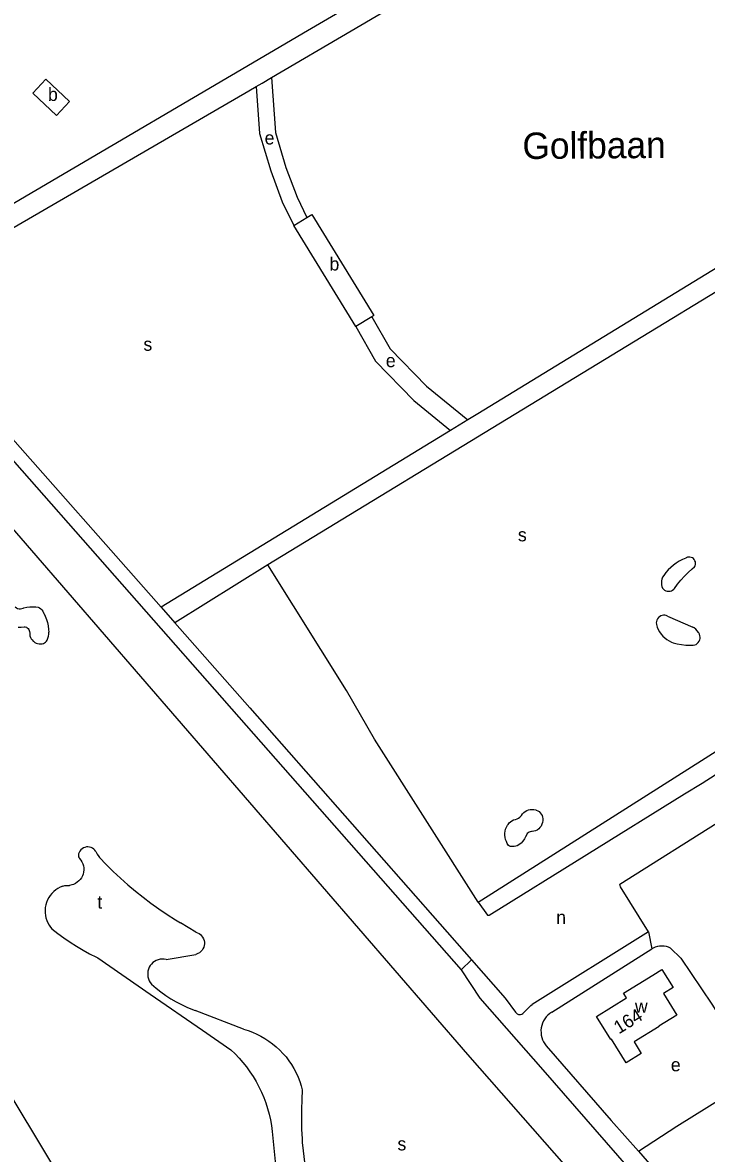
# Model space of a CAD drawing. Extents: x 156066 to 157805, y 383432 to 385631.
# Drawn here: x 157183.1 to 157390.3, y 384159.6 to 384502.5 of the extents above; entities that cross this region are included whole.
import ezdxf

# ---------------------------------------------------------------- set-up
doc = ezdxf.new("R2010")
doc.units = 0
for name, color, linetype in [('BLT_Basislijn', 7, 'Continuous'), ('BLT_Bebouwing', 7, 'Continuous'), ('BLT_Centroide', 7, 'Continuous'), ('BLT_Huisnummer', 7, 'Continuous'), ('BLT_Terrein_beschrifting', 7, 'Continuous'), ('BLT_Vlakafsluiter', 7, 'Continuous')]:
    doc.layers.add(name, color=color, linetype=linetype)

msp = doc.modelspace()

# ---------------------------------------------------------------- linework, layer by layer
at = {"layer": 'BLT_Basislijn'}
for p, q in [((157269.37, 384500), (157138.64, 384423.17)), ((157258.52, 384485.83), (157282.62, 384500)), ((157251.62, 384481.8), (157253.88, 384483.11)), ((157153.14, 384424.57), (157251.62, 384481.8)), ((157148.04, 384412.49), (157225.04, 384325.21)), ((157161.96, 384390.33), (157250.85, 384289.34)), ((157321.03, 384383.89), (157317.99, 384382.04)), ((157317.99, 384382.04), (157312.77, 384378.85)), ((157312.77, 384378.85), (157225.04, 384325.21)), ((157257.34, 384338.04), (157229.21, 384320.49)), ((157225.04, 384325.21), (157229.21, 384320.49)), ((157378.52, 384322.55), (157386.16, 384319.23)), ((157229.21, 384320.49), (157251.97, 384294.7)), ((157388.98, 384271.84), (157431.02, 384299.07)), ((157251.97, 384294.7), (157319.12, 384218.27)), ((157250.85, 384289.34), (157315.94, 384215.28)), ((157235.57, 384226.69), (157230.92, 384229.54)), ((157372.75, 384226.84), (157337.45, 384204.77)), ((157343.39, 384202.41), (157373.72, 384221.64)), ((157379.44, 384221.88), (157382.55, 384218.81)), ((157226.53, 384218.43), (157235.57, 384219.98)), ((157315.94, 384215.28), (157319.12, 384218.27)), ((157319.12, 384218.27), (157329.29, 384206.7)), ((157329.29, 384206.7), (157332.46, 384202.4)), ((157250.02, 384197.26), (157235.31, 384202.94)), ((157341.76, 384192.28), (157361.44, 384169.6)), ((157340.74, 384184.93), (157372.94, 384148.06)), ((157361.44, 384169.6), (157369.67, 384160.28)), ((157267.82, 384162.92), (157269.11, 384151.56)), ((157369.67, 384160.28), (157381.29, 384147.11))]:
    msp.add_line(p, q, dxfattribs=at)
for points in [[(157282.62, 384500), (157336.87, 384531.91)], [(157292.9, 384513.83), (157269.37, 384500)], [(157511.3, 384500), (157466.93, 384473.08), (157321.03, 384383.89)], [(157463.86, 384023.42), (157317.96, 384189.64), (157152.75, 384380.64), (157052.19, 384495.7)], [(157253.88, 384483.11), (157255.67, 384484.15), (157258.52, 384485.83)], [(157258.52, 384485.83), (157259.71, 384469.14), (157262.87, 384458.55), (157266.24, 384449.53), (157269.21, 384443.41)], [(157253.88, 384483.11), (157254.89, 384468.85), (157258.25, 384457.56), (157261.77, 384448.17), (157265.25, 384440.98)], [(157321.16, 384235.84), (157422.22, 384300), (157452.28, 384318.94), (157454.21, 384323.92), (157457.87, 384326.37), (157459.12, 384328.47), (157459.31, 384329.8), (157458.83, 384332.42), (157438.86, 384363.06), (157437.2, 384366.69), (157437.22, 384369.84), (157438.41, 384372.18), (157439.25, 384373.17), (157441.31, 384374.78), (157456.44, 384383.06), (157457.87, 384385.19), (157457.71, 384388.47), (157426.03, 384440.3), (157425.29, 384440.34), (157257.34, 384338.04)], [(157284.04, 384410.33), (157289.99, 384399.85), (157301.67, 384387.92), (157312.77, 384378.85)], [(157288.87, 384413.29), (157294.4, 384403.57), (157305.43, 384392.3), (157317.99, 384382.04)], [(157321.16, 384235.84), (157289.75, 384285.23), (157281.24, 384300), (157257.34, 384338.04)], [(157384, 384340.14), (157383.01, 384339.71), (157382.07, 384339.21), (157381.16, 384338.64), (157380.29, 384338), (157379.48, 384337.3), (157378.72, 384336.55), (157378.02, 384335.73), (157377.38, 384334.87), (157377.01, 384334.3)], [(157386.67, 384337.47), (157386.85, 384337.82), (157386.96, 384338.2), (157386.99, 384338.59), (157386.94, 384338.98), (157386.81, 384339.35), (157386.61, 384339.68), (157386.35, 384339.97), (157386.03, 384340.2), (157385.67, 384340.36), (157385.29, 384340.45), (157384.9, 384340.46), (157384.52, 384340.39), (157384.15, 384340.24), (157384, 384340.14)], [(157380.61, 384330.91), (157381.56, 384332.21), (157382.57, 384333.46), (157383.64, 384334.65), (157384.77, 384335.79), (157385.96, 384336.88), (157386.67, 384337.47)], [(157377.01, 384334.3), (157376.8, 384333.77), (157376.67, 384333.21), (157376.62, 384332.63), (157376.65, 384332.06), (157376.76, 384331.5), (157376.94, 384330.99)], [(157376.94, 384330.99), (157377.23, 384330.67), (157377.58, 384330.41), (157377.97, 384330.22), (157378.39, 384330.1), (157378.82, 384330.07), (157379.25, 384330.11), (157379.67, 384330.23), (157380.05, 384330.43), (157380.4, 384330.69), (157380.61, 384330.91)], [(157180.82, 384325.32), (157181.17, 384325.07), (157181.56, 384324.89), (157181.98, 384324.79), (157182.41, 384324.77), (157182.84, 384324.82), (157183.25, 384324.96), (157183.42, 384325.04)], [(157183.42, 384325.04), (157184.31, 384325.23), (157185.21, 384325.34), (157186.12, 384325.37), (157187.03, 384325.33), (157187.74, 384325.23)], [(157187.74, 384325.23), (157188.18, 384325.02), (157188.58, 384324.74), (157188.93, 384324.4), (157189.22, 384324.01), (157189.44, 384323.57), (157189.48, 384323.47)], [(157189.48, 384323.47), (157189.92, 384322.53), (157190.29, 384321.56), (157190.58, 384320.57), (157190.8, 384319.55), (157190.93, 384318.52), (157190.99, 384317.69)], [(157378.52, 384322.55), (157378.12, 384322.71), (157377.69, 384322.8), (157377.26, 384322.8), (157376.83, 384322.73), (157376.42, 384322.58), (157376.05, 384322.36), (157375.73, 384322.07), (157375.46, 384321.73), (157375.26, 384321.35), (157375.13, 384320.93), (157375.08, 384320.5), (157375.11, 384320.07), (157375.13, 384319.95)], [(157181.74, 384319.22), (157182.62, 384319.19), (157183.55, 384319.25)], [(157183.55, 384319.25), (157183.88, 384319.25), (157184.2, 384319.17), (157184.49, 384319.01), (157184.73, 384318.79), (157184.95, 384318.44)], [(157184.95, 384318.44), (157185.12, 384317.91), (157185.21, 384317.36), (157185.23, 384317.02)], [(157190.48, 384315.25), (157190.73, 384315.83), (157190.89, 384316.42), (157190.98, 384317.04), (157190.99, 384317.69)], [(157375.13, 384319.95), (157375.38, 384319.19), (157375.7, 384318.46), (157376.09, 384317.76), (157376.55, 384317.1), (157377.07, 384316.49), (157377.65, 384315.94), (157378.29, 384315.45), (157378.96, 384315.03), (157379.68, 384314.67), (157380.18, 384314.47)], [(157387.89, 384317.57), (157387.52, 384318.09), (157387.08, 384318.55), (157386.59, 384318.95), (157386.16, 384319.23)], [(157386.3, 384313.68), (157386.73, 384313.79), (157387.14, 384313.97), (157387.5, 384314.22), (157387.81, 384314.54), (157388.06, 384314.9), (157388.25, 384315.3), (157388.35, 384315.73), (157388.38, 384316.18), (157388.33, 384316.61), (157388.2, 384317.04), (157387.99, 384317.43), (157387.89, 384317.57)], [(157185.23, 384317.02), (157185.29, 384316.55), (157185.43, 384316.1), (157185.65, 384315.68), (157185.93, 384315.3), (157186.27, 384314.98), (157186.43, 384314.86)], [(157186.43, 384314.86), (157186.78, 384314.58), (157187.17, 384314.36), (157187.6, 384314.21), (157188.04, 384314.14), (157188.58, 384314.16)], [(157188.58, 384314.16), (157188.98, 384314.18), (157189.36, 384314.27), (157189.72, 384314.43), (157190.04, 384314.67), (157190.3, 384314.96), (157190.48, 384315.25)], [(157380.18, 384314.47), (157381.44, 384314.16), (157382.71, 384313.92), (157384, 384313.76), (157385.3, 384313.68), (157386.3, 384313.68)], [(157088.75, 384280.38), (157125.95, 384248.8), (157138.38, 384224.9), (157179.5, 384177.08), (157199.58, 384143.61), (157248.35, 384085.28), (157269.97, 384055.34), (157304.71, 384024.5), (157340.39, 383985.23), (157391.35, 383930.37), (157420.88, 383940.11), (157470.65, 383958.4), (157478.75, 383966.19), (157481.29, 383979.08), (157476.65, 383991.08), (157465.85, 384006.22), (157459.4, 384019.12), (157463.86, 384023.42)], [(157321.16, 384235.84), (157323.93, 384231.9), (157324.47, 384231.9), (157383.6, 384268.68), (157388.98, 384271.84)], [(157334.23, 384262.1), (157334.55, 384262.55), (157334.93, 384262.95), (157335.37, 384263.29), (157335.85, 384263.56), (157336.36, 384263.76), (157336.9, 384263.89), (157337.45, 384263.93), (157338, 384263.9), (157338.54, 384263.78), (157338.73, 384263.73)], [(157338.73, 384263.73), (157339.18, 384263.52), (157339.59, 384263.25), (157339.95, 384262.91), (157340.25, 384262.52), (157340.49, 384262.09), (157340.65, 384261.62), (157340.74, 384261.14), (157340.75, 384260.64), (157340.74, 384260.52)], [(157329.95, 384253.62), (157329.65, 384254.19), (157329.42, 384254.8), (157329.27, 384255.43), (157329.19, 384256.07), (157329.2, 384256.71), (157329.28, 384257.35), (157329.44, 384257.98), (157329.68, 384258.58), (157329.99, 384259.14), (157330.17, 384259.4)], [(157330.17, 384259.4), (157330.5, 384259.82), (157330.89, 384260.19), (157331.34, 384260.49), (157331.82, 384260.72), (157332.33, 384260.88), (157332.43, 384260.9)], [(157332.43, 384260.9), (157332.91, 384261.06), (157333.36, 384261.29), (157333.76, 384261.59), (157334.11, 384261.95), (157334.23, 384262.1)], [(157340.74, 384260.52), (157340.62, 384259.95), (157340.44, 384259.41), (157340.17, 384258.89), (157339.84, 384258.42), (157339.45, 384258), (157339.02, 384257.65)], [(157372.75, 384226.84), (157364.27, 384240.49), (157364.05, 384241.3), (157395.47, 384261.06)], [(157335.82, 384256.36), (157335.5, 384255.64), (157335.11, 384254.96), (157334.65, 384254.32), (157334.13, 384253.73), (157333.85, 384253.45)], [(157337.27, 384257.22), (157336.91, 384257.18), (157336.56, 384257.06), (157336.25, 384256.87), (157335.99, 384256.61), (157335.82, 384256.36)], [(157339.02, 384257.65), (157338.52, 384257.43), (157337.99, 384257.29), (157337.45, 384257.22), (157337.27, 384257.22)], [(157205.25, 384251.2), (157204.97, 384251.58), (157204.63, 384251.92), (157204.23, 384252.19), (157203.8, 384252.39), (157203.34, 384252.52), (157202.86, 384252.57), (157202.38, 384252.54), (157201.92, 384252.43), (157201.48, 384252.24), (157201.07, 384251.99), (157200.72, 384251.67), (157200.42, 384251.29), (157200.19, 384250.88), (157200.03, 384250.42), (157199.99, 384250.26)], [(157331.54, 384252.68), (157331.21, 384252.65), (157330.89, 384252.69), (157330.59, 384252.81), (157330.33, 384253), (157330.12, 384253.25), (157329.95, 384253.62)], [(157333.85, 384253.45), (157333.43, 384253.15), (157332.97, 384252.92), (157332.48, 384252.77), (157331.98, 384252.69), (157331.54, 384252.68)], [(157200.35, 384249.02), (157200.74, 384248.53), (157201.06, 384247.99), (157201.31, 384247.42), (157201.48, 384246.82), (157201.58, 384246.2), (157201.6, 384245.57), (157201.53, 384244.95), (157201.39, 384244.34), (157201.17, 384243.76), (157200.88, 384243.2), (157200.52, 384242.69), (157200.1, 384242.23), (157199.62, 384241.82), (157199.1, 384241.48), (157198.54, 384241.21), (157197.94, 384241.02), (157197.25, 384240.89)], [(157199.99, 384250.26), (157199.98, 384249.91), (157200.05, 384249.56), (157200.2, 384249.24), (157200.35, 384249.02)], [(157205.25, 384251.2), (157205.68, 384250.4), (157206.18, 384249.64), (157206.37, 384249.38)], [(157206.37, 384249.38), (157208.44, 384247.22), (157210.56, 384245.12), (157212.73, 384243.07), (157214.96, 384241.08), (157217.24, 384239.16), (157219.58, 384237.29), (157221.96, 384235.49), (157224.39, 384233.75), (157226.86, 384232.08), (157229.38, 384230.47), (157230.92, 384229.54)], [(157195.24, 384240.65), (157194.49, 384240.36), (157193.79, 384239.99), (157193.12, 384239.55), (157192.5, 384239.04), (157191.93, 384238.48), (157191.43, 384237.86), (157190.99, 384237.19), (157190.61, 384236.49), (157190.31, 384235.75), (157190.09, 384234.98), (157189.94, 384234.2), (157189.87, 384233.4), (157189.88, 384232.6), (157189.97, 384231.81), (157190.14, 384231.03), (157190.39, 384230.27), (157190.71, 384229.54), (157191.1, 384228.84), (157191.56, 384228.19), (157191.95, 384227.73)], [(157195.24, 384240.65), (157195.88, 384240.81), (157196.55, 384240.89), (157197.25, 384240.89)], [(157191.95, 384227.73), (157193.74, 384226.3), (157195.58, 384224.95), (157197.47, 384223.65), (157199.4, 384222.43), (157201.37, 384221.27), (157203.38, 384220.18), (157205.43, 384219.16), (157205.89, 384218.95)], [(157235.57, 384226.69), (157236.06, 384226.52), (157236.53, 384226.28), (157236.95, 384225.97), (157237.32, 384225.59), (157237.63, 384225.17), (157237.88, 384224.7), (157238.05, 384224.2), (157238.14, 384223.68), (157238.15, 384223.16), (157238.08, 384222.63), (157237.94, 384222.13), (157237.72, 384221.65), (157237.43, 384221.21), (157237.07, 384220.82), (157236.67, 384220.49), (157236.21, 384220.22), (157235.72, 384220.03), (157235.57, 384219.98)], [(157379.44, 384221.88), (157378.81, 384222.15), (157378.15, 384222.34), (157377.48, 384222.46), (157376.79, 384222.5), (157376.1, 384222.46), (157375.42, 384222.34), (157374.77, 384222.14), (157374.13, 384221.87), (157373.72, 384221.64)], [(157205.89, 384218.95), (157221.7, 384207.92), (157237.57, 384196.95), (157246.15, 384191.06)], [(157226.53, 384218.43), (157225.94, 384218.53), (157225.34, 384218.55), (157224.74, 384218.48), (157224.15, 384218.34), (157223.59, 384218.12), (157223.06, 384217.83), (157222.58, 384217.47), (157222.14, 384217.05), (157221.77, 384216.58), (157221.46, 384216.06), (157221.22, 384215.51), (157221.06, 384214.93), (157220.98, 384214.33), (157220.97, 384213.73), (157221.05, 384213.13), (157221.2, 384212.55), (157221.43, 384211.99), (157221.74, 384211.47), (157222.15, 384210.94)], [(157382.55, 384218.81), (157391.95, 384204.86), (157405.66, 384183.03)], [(157315.94, 384215.28), (157321.67, 384206.68), (157340.74, 384184.93)], [(157222.15, 384210.94), (157223.54, 384209.75), (157224.99, 384208.61), (157226.48, 384207.55), (157228.02, 384206.54), (157229.6, 384205.61), (157231.23, 384204.74), (157232.88, 384203.95), (157234.57, 384203.23), (157235.31, 384202.94)], [(157335.26, 384202.7), (157336.14, 384203.61), (157337.08, 384204.46), (157337.45, 384204.77)], [(157332.46, 384202.4), (157332.69, 384202.13), (157332.97, 384201.93), (157333.3, 384201.79), (157333.64, 384201.73), (157333.99, 384201.75), (157334.33, 384201.85), (157334.63, 384202.01)], [(157334.63, 384202.01), (157334.92, 384202.39), (157335.26, 384202.7)], [(157343.39, 384202.41), (157342.79, 384202), (157342.23, 384201.53), (157341.73, 384200.99), (157341.29, 384200.41), (157340.91, 384199.78), (157340.61, 384199.11), (157340.38, 384198.41), (157340.22, 384197.69), (157340.15, 384196.96), (157340.16, 384196.23), (157340.24, 384195.5), (157340.41, 384194.79), (157340.65, 384194.1), (157340.96, 384193.43), (157341.35, 384192.81), (157341.76, 384192.28)], [(157250.02, 384197.26), (157251.38, 384196.85), (157252.71, 384196.35), (157254.01, 384195.79), (157255.28, 384195.15), (157256.51, 384194.44), (157257.7, 384193.67), (157258.84, 384192.83), (157259.94, 384191.92), (157260.98, 384190.96), (157261.96, 384189.93), (157262.89, 384188.86), (157263.76, 384187.73), (157264.56, 384186.56), (157265.29, 384185.34), (157265.95, 384184.08), (157266.54, 384182.79), (157267.06, 384181.47), (157267.5, 384180.12), (157267.82, 384178.93)], [(157246.15, 384191.06), (157247.43, 384189.84), (157248.65, 384188.55), (157249.82, 384187.22), (157250.92, 384185.83), (157251.96, 384184.39), (157252.93, 384182.91), (157253.84, 384181.39), (157254.68, 384179.83), (157255.44, 384178.23), (157256.14, 384176.59), (157256.75, 384174.93), (157257.3, 384173.24), (157257.76, 384171.53), (157258.15, 384169.8), (157258.46, 384168.06), (157258.69, 384166.3), (157258.79, 384165.24)], [(157369.67, 384160.28), (157381.34, 384167.89), (157405.66, 384183.03)], [(157267.82, 384178.93), (157267.65, 384175.95), (157267.55, 384172.96), (157267.54, 384169.98), (157267.61, 384166.99), (157267.75, 384164.01), (157267.82, 384162.92)], [(157258.79, 384165.24), (157259.63, 384157.22), (157260.4, 384149.19), (157261.08, 384141.15), (157261.37, 384137.36)]]:
    msp.add_lwpolyline(points, dxfattribs=at)
at = {"layer": 'BLT_Bebouwing'}
for p, q in [((157269.21, 384443.41), (157270.75, 384444.35)), ((157270.75, 384444.35), (157289.54, 384413.7)), ((157265.25, 384440.98), (157269.21, 384443.41)), ((157284.04, 384410.33), (157265.25, 384440.98)), ((157289.54, 384413.7), (157288.87, 384413.29)), ((157288.87, 384413.29), (157284.04, 384410.33))]:
    msp.add_line(p, q, dxfattribs=at)
for points in [[(157186.14, 384481.14), (157193.34, 384474.36), (157197.27, 384478.53), (157190.07, 384485.31)], [(157357, 384201.16), (157366.07, 384206.75), (157365.17, 384208.2), (157374.01, 384213.69), (157376.81, 384215.43), (157380.23, 384209.88), (157377.32, 384208.09), (157381.32, 384201.59), (157375.9, 384198.24), (157375.98, 384198.11), (157368.37, 384193.42), (157370.52, 384189.92), (157365.93, 384187.09), (157361.49, 384194.29), (157361.31, 384194.17)]]:
    msp.add_lwpolyline(points, close=True, dxfattribs=at)
at = {"layer": 'BLT_Vlakafsluiter'}
msp.add_line((157372.75, 384226.84), (157373.72, 384221.64), dxfattribs=at)

# ---------------------------------------------------------------- texts
at = {"layer": 'BLT_Centroide'}
for s, p in [('b', (157190.76, 384478.74)), ('e', (157256.41, 384465.55)), ('b', (157276.06, 384427.33)), ('s', (157219.68, 384402.99)), ('e', (157293.14, 384398.02)), ('s', (157333.15, 384345.21)), ('t', (157205.71, 384233.85)), ('n', (157344.76, 384229.2)), ('w', (157368.62, 384202.27)), ('e', (157379.5, 384184.52)), ('s', (157296.66, 384160.53))]:
    msp.add_text(s, height=4, dxfattribs=at).set_placement(p)
at = {"layer": 'BLT_Huisnummer'}
msp.add_text('164', height=4, rotation=31.6601, dxfattribs=at).set_placement((157363.75, 384195.68))
at = {"layer": 'BLT_Terrein_beschrifting'}
msp.add_text('Golfbaan', height=8, rotation=0.4375, dxfattribs=at).set_placement((157334.55, 384461.13))

doc.saveas('drawing.dxf')
